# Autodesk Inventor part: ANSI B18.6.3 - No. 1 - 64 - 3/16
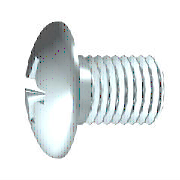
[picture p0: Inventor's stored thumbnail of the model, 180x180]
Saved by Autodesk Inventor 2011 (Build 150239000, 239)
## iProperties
Created: 2010-02
Part Number: ANSI B18.6.3 - No. 1 - 64 - 3/16
Material: Steel, Mild
Description: Cross Recessed Pan Head Machine Screw - Type I
Document SubType Name: Modeling
Standard: ANSI B18.6.3
Designer: Phil
Standard Revision: 2003
Standards Organization: ANSI
Language: en-US
Size Designation: No. 1 - 64 - 3/16
Categories: <MemberInstance><Categories><Category DisplayName="Fasteners" InternalName="e4da775c-781d-43d5-af7c-5136215cf5a6" Mnemonic="FSTN"><Category DisplayName="Bolts"
Density: 1 g/cm^3
IsCustomPart: 0
Author: Phil
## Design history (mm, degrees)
body "Solid1"
sketch "Sketch2"
  geometry: L1 (-3.349, 0)-(7.467, 0) reference; L2 (0, -3.349)-(0, 7.467) reference; L3 (0, 0.851)-(0, 0); L4 (0, 0)-(0.851, 0); L5 (0, 0)-(5.922, 5.922); L6 (0.832, 0.178)-(0.405, 0.129); L7 (0.178, 0.832)-(0.129, 0.405); L8 (0.154, 0.238)-(0.154, 0.236); L9 (0.178, -0.832)-(0.129, -0.405); L10 (0.832, -0.178)-(0.405, -0.129); L11 (-0.178, 0.832)-(-0.129, 0.405); L12 (-0.832, 0.178)-(-0.405, 0.129); L13 (-0.832, -0.178)-(-0.405, -0.129); L14 (-0.178, -0.832)-(-0.129, -0.405); C1 r 1.803 at (0, 0) reference; A1 r 0.284 centre (0, 0) between (0.284, 0) and (0, 0.284); A2 r 0.851 centre (0, 0) between (0.851, 0) and (0.832, 0.178); A3 r 0.851 centre (0, 0) between (0.178, 0.832) and (0, 0.851); A4 r 0.851 centre (0, 0) between (0.832, 0.178) and (0.178, 0.832); A5 r 0.851 centre (0, 0) between (0, -0.851) and (0.178, -0.832); A6 r 0.851 centre (0, 0) between (0.178, -0.832) and (0.832, -0.178); A7 r 0.851 centre (0, 0) between (0.832, -0.178) and (0.851, 0); A8 r 0.851 centre (0, 0) between (0, 0.851) and (-0.178, 0.832); A9 r 0.851 centre (0, 0) between (-0.178, 0.832) and (-0.832, 0.178); A10 r 0.851 centre (0, 0) between (-0.832, 0.178) and (-0.851, 0); A11 r 0.851 centre (0, 0) between (-0.851, 0) and (-0.832, -0.178); A12 r 0.851 centre (0, 0) between (-0.832, -0.178) and (-0.178, -0.832); A13 r 0.851 centre (0, 0) between (-0.178, -0.832) and (0, -0.851); A14 r 0.425 centre (0, 0) between (0.422, 0.057) and (0, 0.425); A15 r 0.25 centre (0.377, 0.377) between (0.129, 0.405) and (0.405, 0.129); A16 r 0.25 centre (0.377, -0.377) between (0.405, -0.129) and (0.129, -0.405); A17 r 0.851 centre (0, 0) between (0.832, -0.178) and (0.851, 0); A18 r 0.851 centre (0, 0) between (0.178, -0.832) and (0.832, -0.178); A19 r 0.851 centre (0, 0) between (0, -0.851) and (0.178, -0.832); A20 r 0.851 centre (0, 0) between (-0.178, -0.832) and (0, -0.851); A21 r 0.851 centre (0, 0) between (-0.832, -0.178) and (-0.178, -0.832); A22 r 0.851 centre (0, 0) between (-0.851, 0) and (-0.832, -0.178); A23 r 0.851 centre (0, 0) between (-0.832, 0.178) and (-0.851, 0); A24 r 0.851 centre (0, 0) between (-0.178, 0.832) and (-0.832, 0.178); A25 r 0.851 centre (0, 0) between (0, 0.851) and (-0.178, 0.832); A26 r 0.25 centre (-0.377, 0.377) between (-0.405, 0.129) and (-0.129, 0.405); A27 r 0.25 centre (-0.377, -0.377) between (-0.129, -0.405) and (-0.405, -0.129)
  constraints: 57 point on circle, 27 centre point, 24 end point, 18 symmetric about line, 4 coincident, 3 collinear, 3 tangent, 2 point on line, 1 midpoint, 1 perpendicular, 27 other
  dimensions: "d4" = 45 deg angle of L5 L4; "d5" = 0.56727 diameter of A1 (= 0.333333 x SDM); "d6" = 1.7018 diameter of A4 (= SDM); "d7" = 0.1778 distance from line of L7.start L3 (= 0.5 x SBR); "d17" = 0.8509 diameter of A14 (= 0.5 x SDM)
extrude "Slot" join sketch "Sketch2" taper "d18" = 5 deg; stored distance "d52" = 10
revolve "Cut" stored, may be unused: angle "d54" = 90 deg
revolve "Body" stored, may be unused: angle "d15" = 90 deg
node "Workplane"
sketch "Sketch1"
  geometry: L1 (-2.608, 0)-(5.991, 0) reference; L2 (0, -0.37)-(0, 2.222) reference; L3 (4.762, 0)-(4.763, 0.927); L4 (4.763, 0.927)-(0.992, 0.927); L5 (-1.346, 1.803)-(-1.346, 0); L6 (-1.211, 0.784)-(-0.752, 0.555); L7 (-0.752, 0.555)-(-0.457, 0); L8 (-0.457, 0)-(4.762, 0); L9 (-1.211, 0.784)-(-1.346, 0.851); L10 (-0.5, 1.803)-(-1.346, 1.803); L11 (-1.346, 0)-(-1.346, 1.803); L12 (-0.5, 1.803)-(0, 1.803); L13 (0, 0.927)-(0.595, 0.927); L14 (0.595, 0.927)-(0.992, 0.927); L15 (0, 0.927)-(0, 1.803); L16 (0.992, 0.927)-(0, 0.927); A1 r 2.344 centre (0.998, 0) between (-0.5, 1.803) and (-1.211, 0.784); A2 r 2.344 centre (0.998, 0) between (-1.211, 0.784) and (-1.346, 0)
  constraints: 28 end point, 5 collinear, 4 perpendicular, 4 point on circle, 3 parallel, 3 point on line, 2 centre point, 1 coincident, 1 tangent
  dimensions: "d1" = 1.8542 diameter of L4 L8 (= GD); "d2" = 0.889 distance from line of L7.end L5 (= INTI); "d12" = 62 deg angle of L7 L8; "d13" = 26.5 deg angle of L6 L8; "d16" = 1.7018 diameter of L9.end L8 (= SDM); "d21" = 1.8542 diameter of L13 L8 (= BDM); "d22" = 3.77031 distance of L3.end L4.end (= GEL); "d23" = 0.39687 distance of L13.end L4.end (= GAL); "d24" = 1.3462 distance between parallel lines of L5 L15 (= KOH); "d25" = 2.34442 radius of A1 (= KR); "d29" = 3.6068 diameter of L10 L8 (= KOD); "d30" = 4.7625 distance between parallel lines of L3 L15 (= NLG)
fillet "Fillet1" dims "d19" = 0.07112 (= 0.2 x SBR)
feature "Thread" dims "d8" = 3.77031 (= GEL), "d9" = 0
fillet "Fillet2" dims "d27" = 0.127 (= KKR)
fillet "Fillet3" dims "d74" = 0.00254 (= R)
other parameters: "GD" = 1.8542 (= NND) [user parameter; used in 1 equation term], "NLG" = 4.7625 [user parameter; used in 1 equation term], "GEL" = 3.77031 [user parameter; used in 2 equation terms], "KOD" = 3.6068 [user parameter; used in 2 equation terms], "KOH" = 1.3462 [user parameter; used in 2 equation terms], "SDM" = 1.7018 [user parameter; used in 4 equation terms], "INTI" = 0.889 [user parameter; used in 1 equation term], "SBR" = 0.3556 [user parameter; used in 2 equation terms], "d3" = -1.3462 (= -KOH), "d20" = 0, "GAL" = 0.39687 [user parameter; used in 1 equation term], "BDM" = 1.8542 (= NND) [user parameter; used in 1 equation term], "KR" = 2.34442 (= 0.65 x KOD) [user parameter; used in 1 equation term], "KKR" = 0.127 [user parameter; used in 1 equation term], "d72" = 0, "d73" = 0, "R" = 0.00254 [user parameter; used in 1 equation term], "SPD" = 1.133 (= -1.35 x PTC + 0.9 x NND) [user parameter], "THREADDIA" = 1.8542 [user parameter], "PTC" = 0.39687 (computed from TPU) [user parameter; used in 1 equation term], "NND" = 1.8542 [user parameter; used in 3 equation terms], "GUL" = 0 [user parameter], "TOA" = 30 deg [user parameter], "GD1" = 1.36727 [user parameter]
